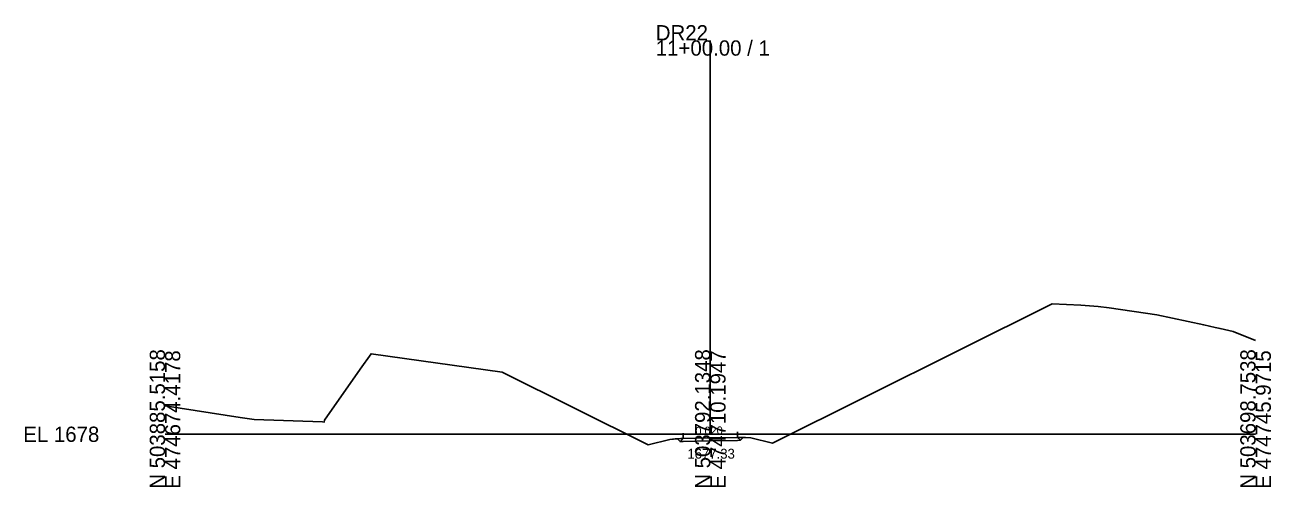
# Model space of a CAD drawing. Extents: x -26 to 1203, y -10 to 9633.
# Drawn here: x -25.7 to 202.8, y 2490.3 to 2575.1 of the extents above; entities that cross this region are included whole.
import ezdxf

# ---------------------------------------------------------------- set-up
doc = ezdxf.new("R2010")
doc.units = 0
for name, color, linetype in [('Exist Cross Section Cell', 7, 'Continuous'), ('Exist XS Center Line Elevation Label', 7, 'Continuous'), ('Exist XS Ground Line', 7, 'Continuous'), ('Prop XS Earthwork Shape', 7, 'Continuous'), ('Prop XS EOT Tick Mark', 7, 'Continuous'), ('Prop XS Finish Grade', 7, 'Continuous'), ('Prop XS Finish Grade Earthwork', 7, 'Continuous'), ('Prop XS Finish Grade Pavement', 7, 'Continuous'), ('Prop XS Pvmt Edge Slope', 7, 'Continuous'), ('Prop XS SE Text', 7, 'Continuous'), ('Prop XS Shoulder Borrow Shape', 7, 'Continuous'), ('Prop XS Subgrade Earthwork', 7, 'Continuous'), ('Scratch_Level_5', 7, 'Continuous')]:
    doc.layers.add(name, color=color, linetype=linetype)

msp = doc.modelspace()

# ---------------------------------------------------------------- linework, layer by layer
at = {"layer": 'Exist Cross Section Cell'}
for p, q in [((100, 2500), (100, 2572.27)), ((0, 2500), (100, 2500)), ((100, 2500), (200, 2500))]:
    msp.add_line(p, q, dxfattribs=at)
at = {"layer": 'Exist XS Ground Line'}
msp.add_lwpolyline([(0, 2505.19), (13.78, 2503.09), (16.36, 2502.7), (28.89, 2502.26), (29.21, 2502.25), (29.22, 2502.57), (35.78, 2511.93), (37.8, 2514.76), (61.83, 2511.41), (88.58, 2498.06), (92.59, 2499.06), (93.57, 2499.14), (94.59, 2499.22), (100, 2499.33), (105.41, 2499.43), (106.43, 2499.39), (107.41, 2499.35), (111.42, 2498.35), (162.71, 2523.96), (167.94, 2523.66), (171.15, 2523.47), (173.14, 2523.17), (181.86, 2521.92), (190.5, 2520.05), (192.57, 2519.61), (193.49, 2519.38), (195.9, 2518.84), (200, 2517.2)], dxfattribs=at)
at = {"layer": 'Prop XS Earthwork Shape'}
msp.add_lwpolyline([(105, 2498.88), (100, 2498.78), (95, 2498.68), (94.45, 2498.67), (93.98, 2499.14), (92.59, 2499.06), (93.57, 2499.14), (94.59, 2499.22), (100, 2499.33), (105.41, 2499.43), (106.43, 2499.39), (107.41, 2499.35), (106.02, 2499.38), (105.53, 2498.89)], close=True, dxfattribs=at)
at = {"layer": 'Prop XS EOT Tick Mark'}
for p, q in [((95, 2499.23), (95, 2500.23)), ((105, 2499.43), (105, 2500.43))]:
    msp.add_line(p, q, dxfattribs=at)
at = {"layer": 'Prop XS Finish Grade'}
for p, q in [((95, 2499.23), (93.98, 2499.14)), ((105, 2499.43), (106.02, 2499.38))]:
    msp.add_line(p, q, dxfattribs=at)
at = {"layer": 'Prop XS Finish Grade Earthwork'}
for p, q in [((93.98, 2499.14), (92.59, 2499.06)), ((106.02, 2499.38), (107.41, 2499.35))]:
    msp.add_line(p, q, dxfattribs=at)
at = {"layer": 'Prop XS Finish Grade Pavement'}
for p, q in [((95, 2499.23), (100, 2499.33)), ((100, 2499.33), (105, 2499.43))]:
    msp.add_line(p, q, dxfattribs=at)
at = {"layer": 'Prop XS Pvmt Edge Slope'}
for p, q in [((95, 2499.23), (94.45, 2498.67)), ((105, 2499.43), (105.53, 2498.89))]:
    msp.add_line(p, q, dxfattribs=at)
at = {"layer": 'Prop XS Shoulder Borrow Shape'}
for points in [[(95, 2499.23), (94.45, 2498.67), (93.98, 2499.14)], [(105.53, 2498.89), (106.02, 2499.38), (105, 2499.43)]]:
    msp.add_lwpolyline(points, close=True, dxfattribs=at)
at = {"layer": 'Prop XS Subgrade Earthwork'}
for p, q in [((94.45, 2498.67), (93.98, 2499.14)), ((95, 2498.68), (94.45, 2498.67)), ((100, 2498.78), (95, 2498.68)), ((105, 2498.88), (100, 2498.78)), ((105, 2498.88), (105.53, 2498.89)), ((105.53, 2498.89), (106.02, 2499.38))]:
    msp.add_line(p, q, dxfattribs=at)
at = {"layer": 'Scratch_Level_5'}
msp.add_lwpolyline([(0, 2505.19), (13.78, 2503.09), (16.36, 2502.7), (28.89, 2502.26), (29.21, 2502.25), (29.22, 2502.57), (35.78, 2511.93), (37.8, 2514.76), (61.83, 2511.41), (88.58, 2498.06), (92.59, 2499.06), (93.57, 2499.14), (94.59, 2499.22), (100, 2499.33), (105.41, 2499.43), (106.43, 2499.39), (107.41, 2499.35), (111.42, 2498.35), (162.71, 2523.96), (167.94, 2523.66), (171.15, 2523.47), (173.14, 2523.17), (181.86, 2521.92), (190.5, 2520.05), (192.57, 2519.61), (193.49, 2519.38), (195.9, 2518.84), (200, 2517.2)], dxfattribs=at)

# ---------------------------------------------------------------- texts
at = {"layer": 'Exist Cross Section Cell'}
for s, p in [('DR22', (90, 2572.27)), ('11+00.00 / 1', (90, 2569.47)), ('EL 1678', (-26, 2498.6))]:
    msp.add_text(s, height=2.8, dxfattribs=at).set_placement(p)
for s, p in [('N 503885.5158', (0, 2490)), ('E 474674.4178', (2.8, 2490)), ('N 503792.1348', (100, 2490)), ('E 474710.1947', (102.8, 2490)), ('N 503698.7538', (200, 2490)), ('E 474745.9715', (202.8, 2490))]:
    msp.add_text(s, height=2.8, rotation=90, dxfattribs=at).set_placement(p)
at = {"layer": 'Exist XS Center Line Elevation Label'}
msp.add_text('1677.33', height=1.8, dxfattribs=at).set_placement((95.8, 2495.53))
at = {"layer": 'Prop XS SE Text'}
msp.add_text('0.020', height=1.5, rotation=1.1458, dxfattribs=at).set_placement((97.28, 2499.85))

doc.saveas('drawing.dxf')
